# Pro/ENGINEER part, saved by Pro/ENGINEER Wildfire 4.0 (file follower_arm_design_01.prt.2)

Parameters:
  METRIC = "NO"

Other parameters: PITCH, DRILL_DIAMETER, THREAD_DIAMETER, THREADS_PER_INCH, THREAD_DEPTH, THREAD_LENGTH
